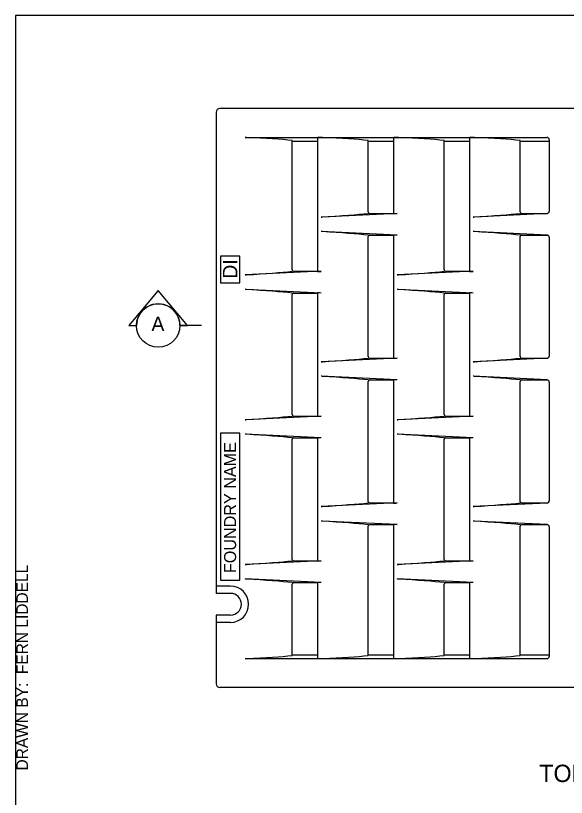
# Model space of a CAD drawing. Extents: x 99862 to 103151, y 100000 to 102076.
# Drawn here: x 99862 to 100623, y 100996 to 102076 of the extents above; entities that cross this region are included whole.
import ezdxf

# ---------------------------------------------------------------- set-up
doc = ezdxf.new("R2010")
doc.units = 0
for name, color, linetype in [('Level 1', 7, 'Continuous'), ('Level 11', 7, 'Continuous'), ('Level 2', 7, 'Continuous'), ('Level 20', 7, 'Continuous'), ('Level 62', 7, 'Continuous'), ('Level 9', 7, 'Continuous')]:
    doc.layers.add(name, color=color, linetype=linetype)

msp = doc.modelspace()

# ---------------------------------------------------------------- linework, layer by layer
at = {"layer": 'Level 1'}
msp.add_lwpolyline([(99862, 99999.5), (103151, 99999.5), (103151, 102075.5), (99862, 102075.5)], close=True, dxfattribs=at)
at = {"layer": 'Level 11'}
for p, q in [((100158.8, 101287.3), (100138.8, 101287.3)), ((100158.8, 101277.3), (100138.8, 101277.3)), ((100158.8, 101247.3), (100138.8, 101247.3)), ((100158.8, 101237.3), (100138.8, 101237.3))]:
    msp.add_line(p, q, dxfattribs=at)
for points in [[(100144.7, 101706.2), (100171.7, 101706.2), (100171.7, 101743.3), (100144.7, 101743.3)], [(100144.7, 101295.8), (100171.7, 101295.8), (100171.7, 101498.8), (100144.7, 101498.8)]]:
    msp.add_lwpolyline(points, close=True, dxfattribs=at)
for radius in [25, 15]:
    msp.add_arc((100158.8, 101262.3), radius, 270, 90, dxfattribs=at)
at = {"layer": 'Level 2'}
for p, q in [((101093.6, 101947.3), (100144.1, 101947.3)), ((100138.8, 101942.1), (100138.8, 101277.3)), ((100178.8, 101907.3), (100283.8, 101907.3)), ((100243.7, 101724.4), (100243.7, 101902.9)), ((100243.7, 101902.3), (100278.8, 101902.3)), ((100278.8, 101906.9), (100278.8, 101722.2)), ((100283.8, 101907.3), (100388.8, 101907.3)), ((100348.7, 101902.3), (100348.7, 101902.9)), ((100348.7, 101902.3), (100383.8, 101902.3)), ((100348.7, 101889.2), (100348.7, 101902.3)), ((100383.8, 101906.9), (100383.8, 101802.2)), ((100388.8, 101907.3), (100493.8, 101907.3)), ((100453.7, 101902.3), (100453.7, 101902.9)), ((100453.7, 101902.3), (100488.8, 101902.3)), ((100453.7, 101889.2), (100453.7, 101902.3)), ((100488.8, 101906.9), (100488.8, 101722.2)), ((100493.8, 101907.3), (100595.7, 101907.3)), ((100558.7, 101902.3), (100558.7, 101902.9)), ((100558.7, 101902.3), (100598.8, 101902.3)), ((100558.7, 101889.2), (100558.7, 101902.3)), ((100598.8, 101904.1), (100598.8, 101805.3)), ((100348.7, 101804.4), (100348.7, 101889.2)), ((100453.7, 101724.4), (100453.7, 101889.2)), ((100558.7, 101804.4), (100558.7, 101889.2)), ((100388.8, 101802.3), (100283.8, 101797.3)), ((100350.8, 101802.3), (100383.8, 101802.3)), ((100595.9, 101802.1), (100493.8, 101797.3)), ((100560.8, 101802.3), (100596.7, 101802.3)), ((100388.8, 101772.3), (100283.8, 101777.3)), ((100383.8, 101772.3), (100383.8, 101602.2)), ((100595.9, 101772.4), (100493.8, 101777.3)), ((100348.7, 101604.4), (100348.7, 101770.2)), ((100350.8, 101772.3), (100383.8, 101772.3)), ((100558.7, 101604.4), (100558.7, 101770.2)), ((100560.8, 101772.3), (100596.7, 101772.3)), ((100598.8, 101769.3), (100598.8, 101605.3)), ((100283.8, 101722.3), (100178.8, 101717.3)), ((100245.8, 101722.3), (100278.8, 101722.3)), ((100493.8, 101722.3), (100388.8, 101717.3)), ((100455.8, 101722.3), (100488.8, 101722.3)), ((100283.8, 101692.3), (100178.8, 101697.3)), ((100493.8, 101692.3), (100388.8, 101697.3)), ((100243.7, 101524.4), (100243.7, 101690.2)), ((100245.8, 101692.3), (100278.8, 101692.3)), ((100278.8, 101692.3), (100278.8, 101522.2)), ((100453.7, 101524.4), (100453.7, 101690.2)), ((100455.8, 101692.3), (100488.8, 101692.3)), ((100488.8, 101692.3), (100488.8, 101522.2)), ((100388.8, 101602.3), (100283.8, 101597.3)), ((100350.8, 101602.3), (100383.8, 101602.3)), ((100595.9, 101602.1), (100493.8, 101597.3)), ((100560.8, 101602.3), (100596.7, 101602.3)), ((100388.8, 101572.3), (100283.8, 101577.3)), ((100348.7, 101404.4), (100348.7, 101570.2)), ((100350.8, 101572.3), (100383.8, 101572.3)), ((100383.8, 101572.3), (100383.8, 101402.2)), ((100595.9, 101572.4), (100493.8, 101577.3)), ((100558.7, 101404.4), (100558.7, 101570.2)), ((100560.8, 101572.3), (100596.7, 101572.3)), ((100598.8, 101569.3), (100598.8, 101405.3)), ((100283.8, 101522.3), (100178.8, 101517.3)), ((100245.8, 101522.3), (100278.8, 101522.3)), ((100493.8, 101522.3), (100388.8, 101517.3)), ((100455.8, 101522.3), (100488.8, 101522.3)), ((100283.8, 101492.3), (100178.8, 101497.3)), ((100245.8, 101492.3), (100278.8, 101492.3)), ((100278.8, 101492.3), (100278.8, 101322.2)), ((100493.8, 101492.3), (100388.8, 101497.3)), ((100455.8, 101492.3), (100488.8, 101492.3)), ((100488.8, 101492.3), (100488.8, 101322.2)), ((100243.7, 101324.4), (100243.7, 101490.2)), ((100453.7, 101324.4), (100453.7, 101490.2)), ((100388.8, 101402.3), (100283.8, 101397.3)), ((100350.8, 101402.3), (100383.8, 101402.3)), ((100595.9, 101402.1), (100493.8, 101397.3)), ((100560.8, 101402.3), (100596.7, 101402.3)), ((100388.8, 101372.3), (100283.8, 101377.3)), ((100595.9, 101372.4), (100493.8, 101377.3)), ((100348.7, 101205.4), (100348.7, 101370.2)), ((100350.8, 101372.3), (100383.8, 101372.3)), ((100383.8, 101372.3), (100383.8, 101187.7)), ((100558.7, 101205.4), (100558.7, 101370.2)), ((100560.8, 101372.3), (100596.7, 101372.3)), ((100598.8, 101369.3), (100598.8, 101190.4)), ((100283.8, 101322.3), (100178.8, 101317.3)), ((100245.8, 101322.3), (100278.8, 101322.3)), ((100493.8, 101322.3), (100388.8, 101317.3)), ((100455.8, 101322.3), (100488.8, 101322.3)), ((100283.8, 101292.3), (100178.8, 101297.3)), ((100493.8, 101292.3), (100388.8, 101297.3)), ((100243.7, 101191.7), (100243.7, 101290.2)), ((100245.8, 101292.3), (100278.8, 101292.3)), ((100278.8, 101292.3), (100278.8, 101187.7)), ((100453.7, 101205.4), (100453.7, 101290.2)), ((100455.8, 101292.3), (100488.8, 101292.3)), ((100488.8, 101292.3), (100488.8, 101187.7)), ((100138.8, 101247.3), (100138.8, 101152.5)), ((100348.7, 101192.3), (100348.7, 101205.4)), ((100453.7, 101192.3), (100453.7, 101205.4)), ((100558.7, 101192.3), (100558.7, 101205.4)), ((100243.7, 101192.3), (100278.8, 101192.3)), ((100348.7, 101192.3), (100383.8, 101192.3)), ((100348.7, 101191.7), (100348.7, 101192.3)), ((100453.7, 101192.3), (100488.8, 101192.3)), ((100453.7, 101191.7), (100453.7, 101192.3)), ((100558.7, 101192.3), (100598.8, 101192.3)), ((100558.7, 101191.7), (100558.7, 101192.3)), ((100178.8, 101187.3), (100283.8, 101187.3)), ((100283.8, 101187.3), (100388.8, 101187.3)), ((100388.8, 101187.3), (100493.8, 101187.3)), ((100493.8, 101187.3), (100595.7, 101187.3)), ((101093.6, 101147.3), (100144.1, 101147.3))]:
    msp.add_line(p, q, dxfattribs=at)
for centre, radius, start, end in [((100144.1, 101942.1), 5.21, 90, 180), ((100595.7, 101904.1), 3.13, 0, 90), ((100595.7, 101805.3), 3.13, 272.7263, 360), ((100350.8, 101804.4), 2.09, 180, 270), ((100560.8, 101804.4), 2.09, 180, 270), ((100595.7, 101769.3), 3.13, 0, 87.2737), ((100350.8, 101770.2), 2.09, 90, 180), ((100560.8, 101770.2), 2.09, 90, 180), ((100245.8, 101724.4), 2.09, 180, 270), ((100455.8, 101724.4), 2.09, 180, 270), ((100245.8, 101690.2), 2.09, 90, 180), ((100455.8, 101690.2), 2.09, 90, 180), ((100350.8, 101604.4), 2.09, 180, 270), ((100560.8, 101604.4), 2.09, 180, 270), ((100595.7, 101605.3), 3.13, 272.7263, 360), ((100350.8, 101570.2), 2.09, 90, 180), ((100560.8, 101570.2), 2.09, 90, 180), ((100595.7, 101569.3), 3.13, 0, 87.2737), ((100245.8, 101524.4), 2.09, 180, 270), ((100455.8, 101524.4), 2.09, 180, 270), ((100245.8, 101490.2), 2.09, 90, 180), ((100455.8, 101490.2), 2.09, 90, 180), ((100595.7, 101405.3), 3.13, 272.7263, 360), ((100350.8, 101404.4), 2.09, 180, 270), ((100560.8, 101404.4), 2.09, 180, 270), ((100350.8, 101370.2), 2.09, 90, 180), ((100560.8, 101370.2), 2.09, 90, 180), ((100595.7, 101369.3), 3.13, 0, 87.2737), ((100245.8, 101324.4), 2.09, 180, 270), ((100455.8, 101324.4), 2.09, 180, 270), ((100245.8, 101290.2), 2.09, 90, 180), ((100455.8, 101290.2), 2.09, 90, 180), ((100595.7, 101190.4), 3.13, 270, 0), ((100144.1, 101152.5), 5.21, 180, 270)]:
    msp.add_arc(centre, radius, start, end, dxfattribs=at)
for centre, major_axis, ratio, start_param, end_param in [((100178.8, 101906.9), (-5, 0), 0.076923, 4.283592, 4.712389), ((100122.7, 101897.4), (-140, 0), 0.076923, 3.669179, 4.283592), ((100283.8, 101906.9), (-5, 0), 0.076923, 4.712389, 6.283185), ((100283.8, 101906.9), (-5, 0), 0.076923, 4.283592, 4.712389), ((100227.7, 101897.4), (-140, 0), 0.076923, 3.669179, 4.283592), ((100388.8, 101906.9), (-5, 0), 0.076923, 4.712389, 6.283185), ((100388.8, 101906.9), (-5, 0), 0.076923, 4.283592, 4.712389), ((100332.7, 101897.4), (-140, 0), 0.076923, 3.669179, 4.283592), ((100493.8, 101906.9), (-5, 0), 0.076923, 4.712389, 6.283185), ((100493.8, 101906.9), (-5, 0), 0.076923, 4.283592, 4.712389), ((100437.7, 101897.4), (-140, 0), 0.076923, 3.669179, 4.283592), ((100283.8, 101797.4), (5, 0.24), 0.033307, 4.710801, 5.139598), ((100227.7, 101798.9), (140, 6.7), 0.033307, 5.139598, 5.754011), ((100388.8, 101802.4), (5, 0.24), 0.033307, 3.140005, 4.710801), ((100493.8, 101797.4), (5, 0.24), 0.033307, 4.710801, 5.139598), ((100437.7, 101798.9), (140, 6.7), 0.033307, 5.139598, 5.754011), ((100283.8, 101777.1), (-5, 0.24), 0.033307, 4.28518, 4.713977), ((100227.7, 101775.7), (-140, 6.7), 0.033307, 3.670767, 4.28518), ((100388.8, 101772.1), (-5, 0.24), 0.033307, 4.713977, 6.284773), ((100493.8, 101777.1), (-5, 0.24), 0.033307, 4.28518, 4.713977), ((100437.7, 101775.7), (-140, 6.7), 0.033307, 3.670767, 4.28518), ((100122.7, 101718.9), (140, 6.7), 0.033307, 5.139598, 5.754011), ((100283.8, 101722.4), (5, 0.24), 0.033307, 3.140005, 4.710801), ((100332.7, 101718.9), (140, 6.7), 0.033307, 5.139598, 5.754011), ((100493.8, 101722.4), (5, 0.24), 0.033307, 3.140005, 4.710801), ((100178.8, 101717.4), (5, 0.24), 0.033307, 4.710801, 5.139598), ((100388.8, 101717.4), (5, 0.24), 0.033307, 4.710801, 5.139598), ((100178.8, 101697.1), (-5, 0.24), 0.033307, 4.28518, 4.713977), ((100122.7, 101695.7), (-140, 6.7), 0.033307, 3.670767, 4.28518), ((100388.8, 101697.1), (-5, 0.24), 0.033307, 4.28518, 4.713977), ((100332.7, 101695.7), (-140, 6.7), 0.033307, 3.670767, 4.28518), ((100283.8, 101692.1), (-5, 0.24), 0.033307, 4.713977, 6.284773), ((100493.8, 101692.1), (-5, 0.24), 0.033307, 4.713977, 6.284773), ((100227.7, 101598.9), (140, 6.7), 0.033307, 5.139598, 5.754011), ((100388.8, 101602.4), (5, 0.24), 0.033307, 3.140005, 4.710801), ((100437.7, 101598.9), (140, 6.7), 0.033307, 5.139598, 5.754011), ((100283.8, 101597.4), (5, 0.24), 0.033307, 4.710801, 5.139598), ((100493.8, 101597.4), (5, 0.24), 0.033307, 4.710801, 5.139598), ((100283.8, 101577.1), (-5, 0.24), 0.033307, 4.28518, 4.713977), ((100227.7, 101575.7), (-140, 6.7), 0.033307, 3.670767, 4.28518), ((100388.8, 101572.1), (-5, 0.24), 0.033307, 4.713977, 6.284773), ((100493.8, 101577.1), (-5, 0.24), 0.033307, 4.28518, 4.713977), ((100437.7, 101575.7), (-140, 6.7), 0.033307, 3.670767, 4.28518), ((100178.8, 101517.4), (5, 0.24), 0.033307, 4.710801, 5.139598), ((100122.7, 101518.9), (140, 6.7), 0.033307, 5.139598, 5.754011), ((100283.8, 101522.4), (5, 0.24), 0.033307, 3.140005, 4.710801), ((100388.8, 101517.4), (5, 0.24), 0.033307, 4.710801, 5.139598), ((100332.7, 101518.9), (140, 6.7), 0.033307, 5.139598, 5.754011), ((100493.8, 101522.4), (5, 0.24), 0.033307, 3.140005, 4.710801), ((100178.8, 101497.1), (-5, 0.24), 0.033307, 4.28518, 4.713977), ((100122.7, 101495.7), (-140, 6.7), 0.033307, 3.670767, 4.28518), ((100283.8, 101492.1), (-5, 0.24), 0.033307, 4.713977, 6.284773), ((100388.8, 101497.1), (-5, 0.24), 0.033307, 4.28518, 4.713977), ((100332.7, 101495.7), (-140, 6.7), 0.033307, 3.670767, 4.28518), ((100493.8, 101492.1), (-5, 0.24), 0.033307, 4.713977, 6.284773), ((100283.8, 101397.4), (5, 0.24), 0.033307, 4.710801, 5.139598), ((100227.7, 101398.9), (140, 6.7), 0.033307, 5.139598, 5.754011), ((100388.8, 101402.4), (5, 0.24), 0.033307, 3.140005, 4.710801), ((100493.8, 101397.4), (5, 0.24), 0.033307, 4.710801, 5.139598), ((100437.7, 101398.9), (140, 6.7), 0.033307, 5.139598, 5.754011), ((100283.8, 101377.1), (-5, 0.24), 0.033307, 4.28518, 4.713977), ((100227.7, 101375.7), (-140, 6.7), 0.033307, 3.670767, 4.28518), ((100493.8, 101377.1), (-5, 0.24), 0.033307, 4.28518, 4.713977), ((100437.7, 101375.7), (-140, 6.7), 0.033307, 3.670767, 4.28518), ((100388.8, 101372.1), (-5, 0.24), 0.033307, 4.713977, 6.284773), ((100122.7, 101318.9), (140, 6.7), 0.033307, 5.139598, 5.754011), ((100283.8, 101322.4), (5, 0.24), 0.033307, 3.140005, 4.710801), ((100332.7, 101318.9), (140, 6.7), 0.033307, 5.139598, 5.754011), ((100493.8, 101322.4), (5, 0.24), 0.033307, 3.140005, 4.710801), ((100178.8, 101317.4), (5, 0.24), 0.033307, 4.710801, 5.139598), ((100388.8, 101317.4), (5, 0.24), 0.033307, 4.710801, 5.139598), ((100178.8, 101297.1), (-5, 0.24), 0.033307, 4.28518, 4.713977), ((100122.7, 101295.7), (-140, 6.7), 0.033307, 3.670767, 4.28518), ((100388.8, 101297.1), (-5, 0.24), 0.033307, 4.28518, 4.713977), ((100332.7, 101295.7), (-140, 6.7), 0.033307, 3.670767, 4.28518), ((100283.8, 101292.1), (-5, 0.24), 0.033307, 4.713977, 6.284773), ((100493.8, 101292.1), (-5, 0.24), 0.033307, 4.713977, 6.284773), ((100122.7, 101197.1), (-140, 0), 0.076923, 1.999593, 2.614006), ((100227.7, 101197.1), (-140, 0), 0.076923, 1.999593, 2.614006), ((100332.7, 101197.1), (-140, 0), 0.076923, 1.999593, 2.614006), ((100437.7, 101197.1), (-140, 0), 0.076923, 1.999593, 2.614006), ((100178.8, 101187.7), (-5, 0), 0.076923, 1.570796, 1.999593), ((100283.8, 101187.7), (-5, 0), 0.076923, 0, 1.570796), ((100283.8, 101187.7), (-5, 0), 0.076923, 1.570796, 1.999593), ((100388.8, 101187.7), (-5, 0), 0.076923, 0, 1.570796), ((100388.8, 101187.7), (-5, 0), 0.076923, 1.570796, 1.999593), ((100493.8, 101187.7), (-5, 0), 0.076923, 0, 1.570796), ((100493.8, 101187.7), (-5, 0), 0.076923, 1.570796, 1.999593)]:
    msp.add_ellipse(centre, major_axis=major_axis, ratio=ratio, start_param=start_param, end_param=end_param, dxfattribs=at)
at = {"layer": 'Level 9'}
for p, q in [((100058.9, 101695.7), (100018.2, 101647.3)), ((100099.5, 101647.3), (100058.9, 101695.7)), ((100018.2, 101647.3), (100028.9, 101647.3)), ((100088.9, 101647.3), (100099.5, 101647.3)), ((100118.9, 101647.3), (100088.9, 101647.3))]:
    msp.add_line(p, q, dxfattribs=at)
msp.add_circle((100058.9, 101647.3), 30, dxfattribs=at)
msp.add_arc((100058.9, 101647.3), 30, 359.9978, 180.0022, dxfattribs=at)

# ---------------------------------------------------------------- texts
at = {"layer": 'Level 11'}
for s, height, p in [('DI', 20, (100168.2, 101712.1)), ('FOUNDRY NAME', 16.685, (100166.5, 101305.4))]:
    msp.add_text(s, height=height, rotation=90, dxfattribs=at).set_placement(p)
at = {"layer": 'Level 20'}
for s, height, p in [('A', 20, (100049.6, 101639.7)), ('TOP', 24, (100585.2, 101016.7))]:
    msp.add_text(s, height=height, dxfattribs=at).set_placement(p)
at = {"layer": 'Level 62'}
msp.add_text('DRAWN BY:  FERN LIDDELL', height=16, rotation=90, dxfattribs=at).set_placement((99879, 101032.7))

doc.saveas('drawing.dxf')
